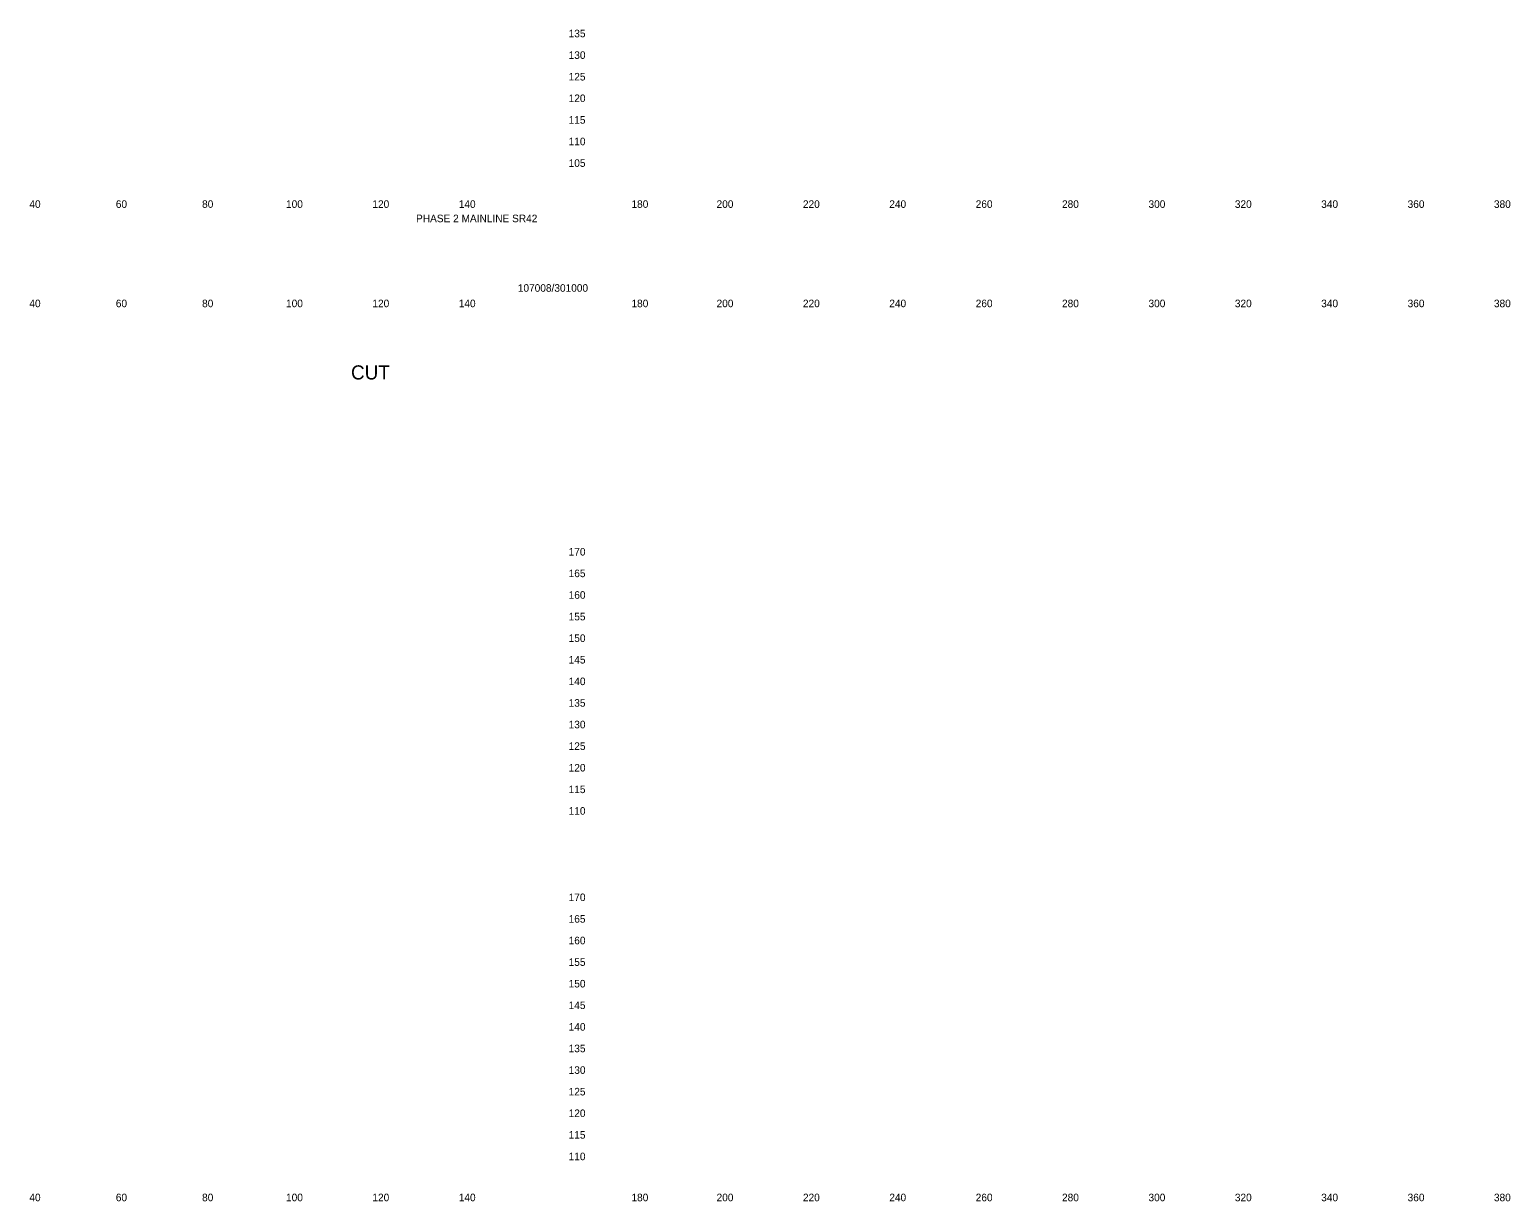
# Model space of a CAD drawing. Extents: x 21281 to 22024, y 6472 to 15208.
# Drawn here: x 21681.3 to 22024.2, y 9465.3 to 9736.6 of the extents above; entities that cross this region are included whole.
import ezdxf

# ---------------------------------------------------------------- set-up
doc = ezdxf.new("R2010")
doc.units = 0
doc.layers.add('XS_SHEET_LABELS_ELEVATION', color=7, linetype='Continuous')
doc.layers.add('XS_SHEET_LABELS_OFFSET', color=7, linetype='Continuous')

msp = doc.modelspace()

# ---------------------------------------------------------------- texts
at = {"layer": 'XS_SHEET_LABELS_ELEVATION'}
for s, p in [('  135  ', (21804.84, 9734.84)), ('  130  ', (21804.84, 9729.84)), ('  125  ', (21804.84, 9724.84)), ('  120  ', (21804.84, 9719.84)), ('  115  ', (21804.84, 9714.84)), ('  110  ', (21804.84, 9709.84)), ('  105  ', (21804.84, 9704.84)), ('  170  ', (21804.84, 9614.84)), ('  165  ', (21804.84, 9609.84)), ('  160  ', (21804.84, 9604.84)), ('  155  ', (21804.84, 9599.84)), ('  150  ', (21804.84, 9594.84)), ('  145  ', (21804.84, 9589.84)), ('  140  ', (21804.84, 9584.84)), ('  135  ', (21804.84, 9579.84)), ('  130  ', (21804.84, 9574.84)), ('  125  ', (21804.84, 9569.84)), ('  120  ', (21804.84, 9564.84)), ('  115  ', (21804.84, 9559.84)), ('  110  ', (21804.84, 9554.84)), ('  170  ', (21804.84, 9534.84)), ('  165  ', (21804.84, 9529.84)), ('  160  ', (21804.84, 9524.84)), ('  155  ', (21804.84, 9519.84)), ('  150  ', (21804.84, 9514.84)), ('  145  ', (21804.84, 9509.84)), ('  140  ', (21804.84, 9504.84)), ('  135  ', (21804.84, 9499.84)), ('  130  ', (21804.84, 9494.84)), ('  125  ', (21804.84, 9489.84)), ('  120  ', (21804.84, 9484.84)), ('  115  ', (21804.84, 9479.84)), ('  110  ', (21804.84, 9474.84))]:
    msp.add_text(s, height=1.75, dxfattribs=at).set_placement(p)
at = {"layer": 'XS_SHEET_LABELS_OFFSET'}
for s, height, p in [('  40  ', 1.75, (21679.95, 9695.34)), ('  60  ', 1.75, (21699.97, 9695.34)), ('  80  ', 1.75, (21719.95, 9695.34)), ('  100  ', 1.75, (21739.39, 9695.34)), ('  120  ', 1.75, (21759.39, 9695.34)), ('  140  ', 1.75, (21779.39, 9695.34)), ('  180  ', 1.75, (21819.39, 9695.34)), ('  200  ', 1.75, (21839.1, 9695.34)), ('  220  ', 1.75, (21859.1, 9695.34)), ('  240  ', 1.75, (21879.1, 9695.34)), ('  260  ', 1.75, (21899.11, 9695.34)), ('  280  ', 1.75, (21919.1, 9695.34)), ('  300  ', 1.75, (21939.13, 9695.34)), ('  320  ', 1.75, (21959.13, 9695.34)), ('  340  ', 1.75, (21979.13, 9695.34)), ('  360  ', 1.75, (21999.14, 9695.34)), ('  380  ', 1.75, (22019.13, 9695.34)), ('PHASE 2 MAINLINE SR42', 1.75, (21770.8, 9692.02)), ('107008/301000', 1.75, (21794.37, 9675.92)), ('  40  ', 1.75, (21679.95, 9672.34)), ('  60  ', 1.75, (21699.97, 9672.34)), ('  80  ', 1.75, (21719.95, 9672.34)), ('  100  ', 1.75, (21739.39, 9672.34)), ('  120  ', 1.75, (21759.39, 9672.34)), ('  140  ', 1.75, (21779.39, 9672.34)), ('  180  ', 1.75, (21819.39, 9672.34)), ('  200  ', 1.75, (21839.1, 9672.34)), ('  220  ', 1.75, (21859.1, 9672.34)), ('  240  ', 1.75, (21879.1, 9672.34)), ('  260  ', 1.75, (21899.11, 9672.34)), ('  280  ', 1.75, (21919.1, 9672.34)), ('  300  ', 1.75, (21939.13, 9672.34)), ('  320  ', 1.75, (21959.13, 9672.34)), ('  340  ', 1.75, (21979.13, 9672.34)), ('  360  ', 1.75, (21999.14, 9672.34)), ('  380  ', 1.75, (22019.13, 9672.34)), ('CUT', 3.273, (21755.74, 9655.61)), ('  40  ', 1.75, (21679.95, 9465.34)), ('  60  ', 1.75, (21699.97, 9465.34)), ('  80  ', 1.75, (21719.95, 9465.34)), ('  100  ', 1.75, (21739.39, 9465.34)), ('  120  ', 1.75, (21759.39, 9465.34)), ('  140  ', 1.75, (21779.39, 9465.34)), ('  180  ', 1.75, (21819.39, 9465.34)), ('  200  ', 1.75, (21839.1, 9465.34)), ('  220  ', 1.75, (21859.1, 9465.34)), ('  240  ', 1.75, (21879.1, 9465.34)), ('  260  ', 1.75, (21899.11, 9465.34)), ('  280  ', 1.75, (21919.1, 9465.34)), ('  300  ', 1.75, (21939.13, 9465.34)), ('  320  ', 1.75, (21959.13, 9465.34)), ('  340  ', 1.75, (21979.13, 9465.34)), ('  360  ', 1.75, (21999.14, 9465.34)), ('  380  ', 1.75, (22019.13, 9465.34))]:
    msp.add_text(s, height=height, dxfattribs=at).set_placement(p)

doc.saveas('drawing.dxf')
